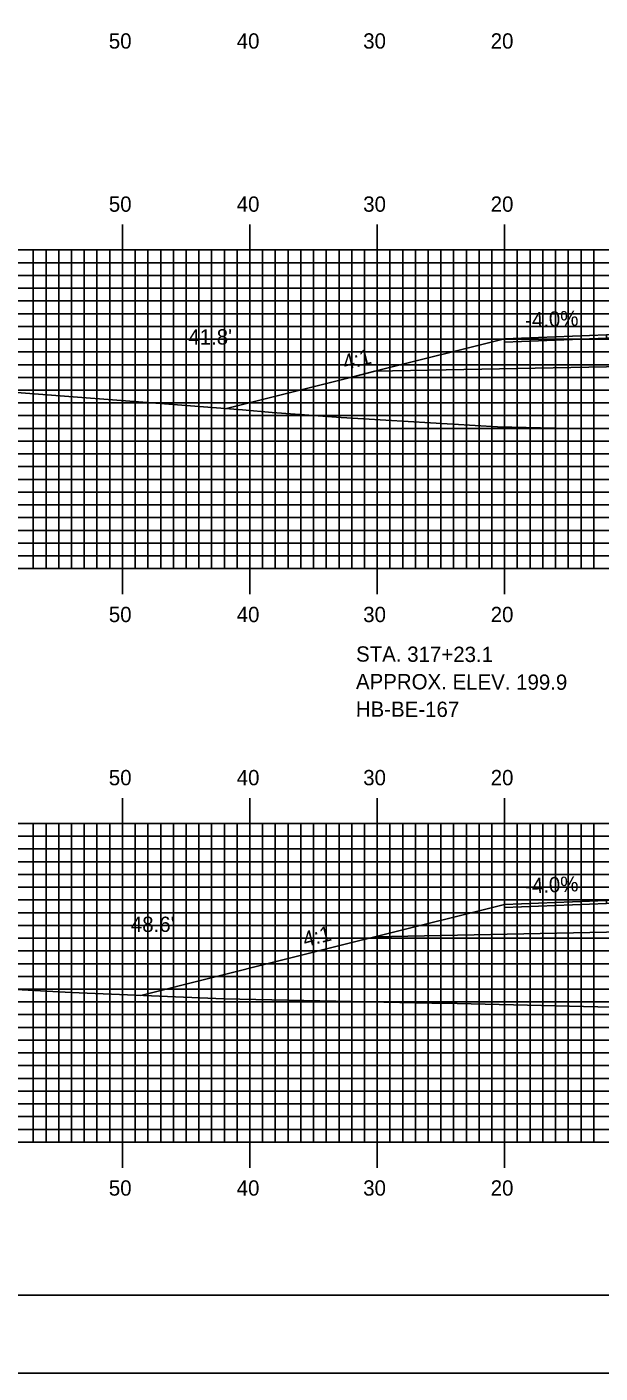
# Model space of a CAD drawing. Extents: x 1819637 to 1819981, y 442591 to 442811.
# Drawn here: x 1819745.7 to 1819790.7, y 442590.5 to 442696.2 of the extents above; entities that cross this region are included whole.
import ezdxf

# ---------------------------------------------------------------- set-up
doc = ezdxf.new("R2010")
doc.units = 0
for name, color, linetype in [('ANNOTATION', 7, 'Continuous'), ('BORDER', 7, 'Continuous'), ('BORING - NO REFUSAL', 7, 'Continuous'), ('D_Roadway_Centerline', 7, 'Continuous'), ('D_Roadway_Edge_Shoulder', 7, 'Continuous'), ('D_Roadway_SlopeLines', 7, 'Continuous'), ('D_Roadway_SubGrade', 7, 'Continuous'), ('D_Text_Standard', 7, 'Continuous'), ('H_V ANNOTATION', 7, 'Continuous'), ('MAJOR', 7, 'Continuous'), ('MINOR', 7, 'Continuous'), ('PLOT BOUNDARY', 7, 'Continuous'), ('S_Roadway_Centerline', 7, 'Continuous')]:
    doc.layers.add(name, color=color, linetype=linetype)

msp = doc.modelspace()

# ---------------------------------------------------------------- linework, layer by layer
at = {"layer": 'BORDER'}
msp.add_lwpolyline([(1819653.58, 442596.67), (1819973.58, 442596.67), (1819973.58, 442806.67), (1819653.58, 442806.67)], close=True, dxfattribs=at)
at = {"layer": 'D_Roadway_Centerline'}
for points in [[(1819761.34, 442666.23), (1819771.18, 442668.69), (1819773, 442669.15), (1819783.18, 442671.69), (1819791.18, 442672.01), (1819803.18, 442672.25), (1819815.18, 442672.01), (1819823.18, 442671.69), (1819833.35, 442669.15), (1819835.18, 442668.69), (1819850.33, 442663.64)], [(1819754.61, 442620.17), (1819771.18, 442624.32), (1819773, 442624.77), (1819783.18, 442627.32), (1819791.18, 442627.64), (1819803.18, 442627.88), (1819815.18, 442627.64), (1819823.18, 442627.32), (1819833.35, 442624.77), (1819835.18, 442624.32), (1819853.13, 442618.33)]]:
    msp.add_lwpolyline(points, dxfattribs=at)
at = {"layer": 'D_Roadway_Edge_Shoulder'}
for points in [[(1819791.18, 442672.01), (1819783.18, 442671.69), (1819783.18, 442671.44), (1819791.18, 442671.76)], [(1819791.18, 442627.64), (1819783.18, 442627.32), (1819783.18, 442627.07), (1819791.18, 442627.39)]]:
    msp.add_lwpolyline(points, close=True, dxfattribs=at)
at = {"layer": 'D_Roadway_SlopeLines'}
for points in [[(1819783.18, 442671.69), (1819773, 442669.15), (1819771.18, 442668.69), (1819761.34, 442666.23)], [(1819783.18, 442627.32), (1819773, 442624.77), (1819771.18, 442624.32), (1819754.61, 442620.17)]]:
    msp.add_lwpolyline(points, dxfattribs=at)
at = {"layer": 'D_Roadway_SubGrade'}
for points in [[(1819791.18, 442669.51), (1819773, 442669.15), (1819783.18, 442671.69), (1819783.18, 442671.44), (1819791.18, 442671.76), (1819803.18, 442672), (1819815.18, 442671.76), (1819823.18, 442671.44), (1819823.18, 442671.69), (1819833.35, 442669.15), (1819815.18, 442669.51), (1819803.18, 442669.75)], [(1819791.18, 442625.14), (1819773, 442624.77), (1819783.18, 442627.32), (1819783.18, 442627.07), (1819791.18, 442627.39), (1819803.18, 442627.63), (1819815.18, 442627.39), (1819823.18, 442627.07), (1819823.18, 442627.32), (1819833.35, 442624.77), (1819815.18, 442625.14), (1819803.18, 442625.38)]]:
    msp.add_lwpolyline(points, close=True, dxfattribs=at)
at = {"layer": 'MAJOR'}
for p, q in [((1819753.18, 442680.67), (1819753.18, 442678.67)), ((1819763.18, 442680.67), (1819763.18, 442678.67)), ((1819773.18, 442680.67), (1819773.18, 442678.67)), ((1819783.18, 442680.67), (1819783.18, 442678.67)), ((1819663.18, 442678.67), (1819943.18, 442678.67)), ((1819663.18, 442678.67), (1819943.18, 442678.67)), ((1819753.18, 442653.67), (1819753.18, 442678.67)), ((1819763.18, 442653.67), (1819763.18, 442678.67)), ((1819773.18, 442653.67), (1819773.18, 442678.67)), ((1819783.18, 442653.67), (1819783.18, 442678.67)), ((1819663.18, 442673.67), (1819943.18, 442673.67)), ((1819663.18, 442668.67), (1819943.18, 442668.67)), ((1819663.18, 442663.67), (1819943.18, 442663.67)), ((1819663.18, 442658.67), (1819943.18, 442658.67)), ((1819663.18, 442653.67), (1819943.18, 442653.67)), ((1819663.18, 442653.67), (1819943.18, 442653.67)), ((1819753.18, 442651.66), (1819753.18, 442653.67)), ((1819763.18, 442651.66), (1819763.18, 442653.67)), ((1819773.18, 442651.66), (1819773.18, 442653.67)), ((1819783.18, 442651.66), (1819783.18, 442653.67)), ((1819753.18, 442635.67), (1819753.18, 442633.67)), ((1819763.18, 442635.67), (1819763.18, 442633.67)), ((1819773.18, 442635.67), (1819773.18, 442633.67)), ((1819783.18, 442635.67), (1819783.18, 442633.67)), ((1819663.18, 442633.67), (1819943.18, 442633.67)), ((1819663.18, 442633.67), (1819943.18, 442633.67)), ((1819753.18, 442608.67), (1819753.18, 442633.67)), ((1819763.18, 442608.67), (1819763.18, 442633.67)), ((1819773.18, 442608.67), (1819773.18, 442633.67)), ((1819783.18, 442608.67), (1819783.18, 442633.67)), ((1819663.18, 442628.67), (1819943.18, 442628.67)), ((1819663.18, 442623.67), (1819943.18, 442623.67)), ((1819663.18, 442618.67), (1819943.18, 442618.67)), ((1819663.18, 442613.67), (1819943.18, 442613.67)), ((1819663.18, 442608.67), (1819943.18, 442608.67)), ((1819663.18, 442608.67), (1819943.18, 442608.67)), ((1819753.18, 442606.66), (1819753.18, 442608.67)), ((1819763.18, 442606.66), (1819763.18, 442608.67)), ((1819773.18, 442606.66), (1819773.18, 442608.67)), ((1819783.18, 442606.66), (1819783.18, 442608.67))]:
    msp.add_line(p, q, dxfattribs=at)
at = {"layer": 'MINOR'}
for p, q in [((1819746.18, 442653.67), (1819746.18, 442678.67)), ((1819747.18, 442653.67), (1819747.18, 442678.67)), ((1819748.18, 442653.67), (1819748.18, 442678.67)), ((1819749.18, 442653.67), (1819749.18, 442678.67)), ((1819750.18, 442653.67), (1819750.18, 442678.67)), ((1819751.18, 442653.67), (1819751.18, 442678.67)), ((1819752.18, 442653.67), (1819752.18, 442678.67)), ((1819754.18, 442653.67), (1819754.18, 442678.67)), ((1819755.18, 442653.67), (1819755.18, 442678.67)), ((1819756.18, 442653.67), (1819756.18, 442678.67)), ((1819757.18, 442653.67), (1819757.18, 442678.67)), ((1819758.18, 442653.67), (1819758.18, 442678.67)), ((1819759.18, 442653.67), (1819759.18, 442678.67)), ((1819760.18, 442653.67), (1819760.18, 442678.67)), ((1819761.18, 442653.67), (1819761.18, 442678.67)), ((1819762.18, 442653.67), (1819762.18, 442678.67)), ((1819764.18, 442653.67), (1819764.18, 442678.67)), ((1819765.18, 442653.67), (1819765.18, 442678.67)), ((1819766.18, 442653.67), (1819766.18, 442678.67)), ((1819767.18, 442653.67), (1819767.18, 442678.67)), ((1819768.18, 442653.67), (1819768.18, 442678.67)), ((1819769.18, 442653.67), (1819769.18, 442678.67)), ((1819770.18, 442653.67), (1819770.18, 442678.67)), ((1819771.18, 442653.67), (1819771.18, 442678.67)), ((1819772.18, 442653.67), (1819772.18, 442678.67)), ((1819774.18, 442653.67), (1819774.18, 442678.67)), ((1819775.18, 442653.67), (1819775.18, 442678.67)), ((1819776.18, 442653.67), (1819776.18, 442678.67)), ((1819777.18, 442653.67), (1819777.18, 442678.67)), ((1819778.18, 442653.67), (1819778.18, 442678.67)), ((1819779.18, 442653.67), (1819779.18, 442678.67)), ((1819780.18, 442653.67), (1819780.18, 442678.67)), ((1819781.18, 442653.67), (1819781.18, 442678.67)), ((1819782.18, 442653.67), (1819782.18, 442678.67)), ((1819784.18, 442653.67), (1819784.18, 442678.67)), ((1819785.18, 442653.67), (1819785.18, 442678.67)), ((1819786.18, 442653.67), (1819786.18, 442678.67)), ((1819787.18, 442653.67), (1819787.18, 442678.67)), ((1819788.18, 442653.67), (1819788.18, 442678.67)), ((1819789.18, 442653.67), (1819789.18, 442678.67)), ((1819790.18, 442653.67), (1819790.18, 442678.67)), ((1819663.18, 442677.67), (1819943.18, 442677.67)), ((1819663.18, 442676.67), (1819943.18, 442676.67)), ((1819663.18, 442675.67), (1819943.18, 442675.67)), ((1819663.18, 442674.67), (1819943.18, 442674.67)), ((1819663.18, 442672.67), (1819943.18, 442672.67)), ((1819663.18, 442671.67), (1819943.18, 442671.67)), ((1819663.18, 442670.67), (1819943.18, 442670.67)), ((1819663.18, 442669.67), (1819943.18, 442669.67)), ((1819663.18, 442667.67), (1819943.18, 442667.67)), ((1819663.18, 442666.67), (1819943.18, 442666.67)), ((1819663.18, 442665.67), (1819943.18, 442665.67)), ((1819663.18, 442664.67), (1819943.18, 442664.67)), ((1819663.18, 442662.67), (1819943.18, 442662.67)), ((1819663.18, 442661.67), (1819943.18, 442661.67)), ((1819663.18, 442660.67), (1819943.18, 442660.67)), ((1819663.18, 442659.67), (1819943.18, 442659.67)), ((1819663.18, 442657.67), (1819943.18, 442657.67)), ((1819663.18, 442656.67), (1819943.18, 442656.67)), ((1819663.18, 442655.67), (1819943.18, 442655.67)), ((1819663.18, 442654.67), (1819943.18, 442654.67)), ((1819746.18, 442608.67), (1819746.18, 442633.67)), ((1819747.18, 442608.67), (1819747.18, 442633.67)), ((1819748.18, 442608.67), (1819748.18, 442633.67)), ((1819749.18, 442608.67), (1819749.18, 442633.67)), ((1819750.18, 442608.67), (1819750.18, 442633.67)), ((1819751.18, 442608.67), (1819751.18, 442633.67)), ((1819752.18, 442608.67), (1819752.18, 442633.67)), ((1819754.18, 442608.67), (1819754.18, 442633.67)), ((1819755.18, 442608.67), (1819755.18, 442633.67)), ((1819756.18, 442608.67), (1819756.18, 442633.67)), ((1819757.18, 442608.67), (1819757.18, 442633.67)), ((1819758.18, 442608.67), (1819758.18, 442633.67)), ((1819759.18, 442608.67), (1819759.18, 442633.67)), ((1819760.18, 442608.67), (1819760.18, 442633.67)), ((1819761.18, 442608.67), (1819761.18, 442633.67)), ((1819762.18, 442608.67), (1819762.18, 442633.67)), ((1819764.18, 442608.67), (1819764.18, 442633.67)), ((1819765.18, 442608.67), (1819765.18, 442633.67)), ((1819766.18, 442608.67), (1819766.18, 442633.67)), ((1819767.18, 442608.67), (1819767.18, 442633.67)), ((1819768.18, 442608.67), (1819768.18, 442633.67)), ((1819769.18, 442608.67), (1819769.18, 442633.67)), ((1819770.18, 442608.67), (1819770.18, 442633.67)), ((1819771.18, 442608.67), (1819771.18, 442633.67)), ((1819772.18, 442608.67), (1819772.18, 442633.67)), ((1819774.18, 442608.67), (1819774.18, 442633.67)), ((1819775.18, 442608.67), (1819775.18, 442633.67)), ((1819776.18, 442608.67), (1819776.18, 442633.67)), ((1819777.18, 442608.67), (1819777.18, 442633.67)), ((1819778.18, 442608.67), (1819778.18, 442633.67)), ((1819779.18, 442608.67), (1819779.18, 442633.67)), ((1819780.18, 442608.67), (1819780.18, 442633.67)), ((1819781.18, 442608.67), (1819781.18, 442633.67)), ((1819782.18, 442608.67), (1819782.18, 442633.67)), ((1819784.18, 442608.67), (1819784.18, 442633.67)), ((1819785.18, 442608.67), (1819785.18, 442633.67)), ((1819786.18, 442608.67), (1819786.18, 442633.67)), ((1819787.18, 442608.67), (1819787.18, 442633.67)), ((1819788.18, 442608.67), (1819788.18, 442633.67)), ((1819789.18, 442608.67), (1819789.18, 442633.67)), ((1819790.18, 442608.67), (1819790.18, 442633.67)), ((1819663.18, 442632.67), (1819943.18, 442632.67)), ((1819663.18, 442631.67), (1819943.18, 442631.67)), ((1819663.18, 442630.67), (1819943.18, 442630.67)), ((1819663.18, 442629.67), (1819943.18, 442629.67)), ((1819663.18, 442627.67), (1819943.18, 442627.67)), ((1819663.18, 442626.67), (1819943.18, 442626.67)), ((1819663.18, 442625.67), (1819943.18, 442625.67)), ((1819663.18, 442624.67), (1819943.18, 442624.67)), ((1819663.18, 442622.67), (1819943.18, 442622.67)), ((1819663.18, 442621.67), (1819943.18, 442621.67)), ((1819663.18, 442620.67), (1819943.18, 442620.67)), ((1819663.18, 442619.67), (1819943.18, 442619.67)), ((1819663.18, 442617.67), (1819943.18, 442617.67)), ((1819663.18, 442616.67), (1819943.18, 442616.67)), ((1819663.18, 442615.67), (1819943.18, 442615.67)), ((1819663.18, 442614.67), (1819943.18, 442614.67)), ((1819663.18, 442612.67), (1819943.18, 442612.67)), ((1819663.18, 442611.67), (1819943.18, 442611.67)), ((1819663.18, 442610.67), (1819943.18, 442610.67)), ((1819663.18, 442609.67), (1819943.18, 442609.67))]:
    msp.add_line(p, q, dxfattribs=at)
at = {"layer": 'PLOT BOUNDARY'}
msp.add_lwpolyline([(1819637.39, 442590.55), (1819977.39, 442590.55), (1819977.39, 442810.55), (1819637.39, 442810.55)], close=True, dxfattribs=at)
at = {"layer": 'S_Roadway_Centerline'}
for points in [[(1819663.18, 442669.11), (1819663.36, 442669.1), (1819672.73, 442669.08), (1819681.25, 442668.96), (1819695, 442668.76), (1819697.67, 442668.76), (1819699.01, 442668.7), (1819706.58, 442669.07), (1819715.51, 442669.29), (1819718.52, 442669.16), (1819731.65, 442668.07), (1819739.41, 442667.9), (1819762.61, 442666.13), (1819764.92, 442665.92), (1819770.34, 442665.53), (1819782.62, 442664.8), (1819788.26, 442664.67), (1819798.98, 442664.58), (1819805.45, 442664.38), (1819817.9, 442664.3), (1819821.92, 442664.24), (1819850.87, 442663.63), (1819860.19, 442663.38)], [(1819663.18, 442623.62), (1819666.48, 442623.49), (1819670.71, 442623.16), (1819676.4, 442622.65), (1819688.03, 442622.65), (1819693.91, 442622.62), (1819697.22, 442622.47), (1819708.98, 442622.2), (1819710.94, 442622.14), (1819711.72, 442622.12), (1819727.84, 442621.48), (1819733.69, 442621.2), (1819744.35, 442620.68), (1819749.16, 442620.4), (1819761.15, 442619.9), (1819777.48, 442619.58), (1819779.45, 442619.55), (1819808.13, 442618.86), (1819817.28, 442618.63), (1819845.46, 442618.36), (1819846.85, 442618.34), (1819857.51, 442618.33)]]:
    msp.add_lwpolyline(points, dxfattribs=at)

# ---------------------------------------------------------------- texts
at = {"layer": 'ANNOTATION'}
for s, rotation, p in [('-4.0%', 2.2906, (1819784.81, 442672.56)), ('4:1', 14.0362, (1819770.65, 442669.24)), ('-4.0%', 2.2906, (1819784.81, 442628.18)), ('4:1', 14.0362, (1819767.51, 442623.97))]:
    msp.add_text(s, height=1.2, rotation=rotation, dxfattribs=at).set_placement(p)
at = {"layer": 'BORING - NO REFUSAL'}
for s, p in [('STA. 317+23.1', (1819771.52, 442646.37)), ('APPROX. ELEV. 199.9', (1819771.51, 442644.21)), ('HB-BE-167', (1819771.5, 442642.05))]:
    msp.add_text(s, height=1.2, rotation=359.8142, dxfattribs=at).set_placement(p)
at = {"layer": 'D_Text_Standard'}
for s, p in [("41.8'", (1819758.35, 442671.25)), ("48.6'", (1819753.84, 442625.16))]:
    msp.add_text(s, height=1.2, dxfattribs=at).set_placement(p)
at = {"layer": 'H_V ANNOTATION'}
for s, p in [('50', (1819752.11, 442694.47)), ('40', (1819762.15, 442694.47)), ('30', (1819772.08, 442694.47)), ('20', (1819782.09, 442694.47)), ('50', (1819752.11, 442681.67)), ('40', (1819762.15, 442681.67)), ('30', (1819772.08, 442681.67)), ('20', (1819782.09, 442681.67)), ('50', (1819752.11, 442649.47)), ('40', (1819762.15, 442649.47)), ('30', (1819772.08, 442649.47)), ('20', (1819782.09, 442649.47)), ('50', (1819752.11, 442636.67)), ('40', (1819762.15, 442636.67)), ('30', (1819772.08, 442636.67)), ('20', (1819782.09, 442636.67)), ('50', (1819752.11, 442604.47)), ('40', (1819762.15, 442604.47)), ('30', (1819772.08, 442604.47)), ('20', (1819782.09, 442604.47))]:
    msp.add_text(s, height=1.2, dxfattribs=at).set_placement(p)

doc.saveas('drawing.dxf')
